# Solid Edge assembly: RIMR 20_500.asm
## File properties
Title: Zylinder
Author: ahadarics
Template: iso metric assembly.asm
Last saved by: ahadarics
Revision: 19
Application: Solid Edge
Username: ahadarics
Dokumentum tartalom típus: 1
Document Number: RIMR 20/500
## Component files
Profilrohr.par
Kolbenstange.par
Kit_1.par
Kit_2.par
Mutter_1.par
Mutter_2.par
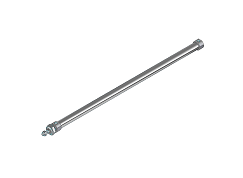
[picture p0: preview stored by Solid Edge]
